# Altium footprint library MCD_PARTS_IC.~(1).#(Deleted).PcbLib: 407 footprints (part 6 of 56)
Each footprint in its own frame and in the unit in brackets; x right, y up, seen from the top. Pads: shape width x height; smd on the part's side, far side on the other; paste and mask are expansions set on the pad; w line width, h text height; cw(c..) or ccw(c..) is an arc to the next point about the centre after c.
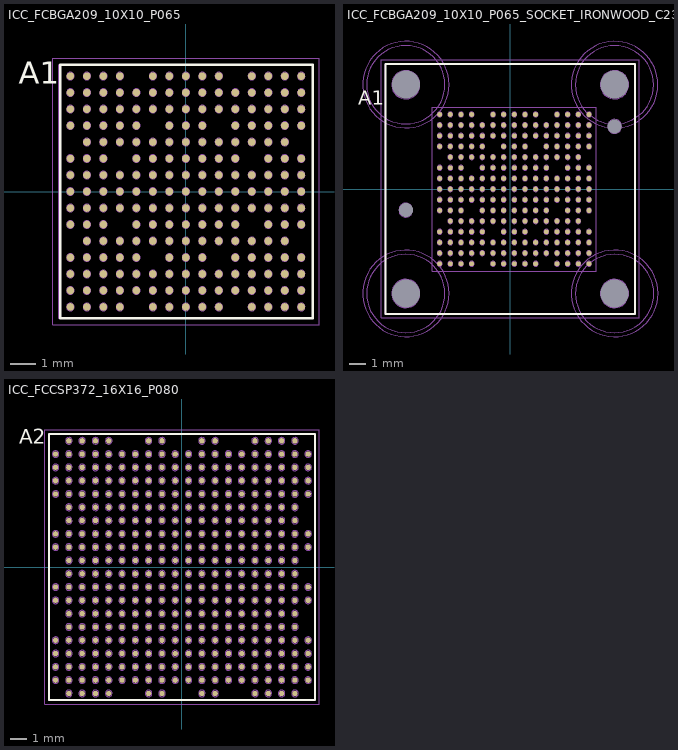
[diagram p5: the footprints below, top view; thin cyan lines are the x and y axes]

## ICC_FCBGA209_10X10_P065 [mm] "MCD-04280"
height 1.2
pads (209):
  round 0.3 smd mask+0.05: A1(-4.55,4.55) A2(-3.9,4.55) A3(-3.25,4.55) A4(-2.6,4.55) A6(-1.3,4.55) A7(-0.65,4.55) A8(0,4.55) A9(0.65,4.55) A10(1.3,4.55) A12(2.6,4.55) A13(3.25,4.55) A14(3.9,4.55) A15(4.55,4.55) B1(-4.55,3.9) B2(-3.9,3.9) B3(-3.25,3.9) B4(-2.6,3.9) B5(-1.95,3.9) B6(-1.3,3.9) B7(-0.65,3.9) B8(0,3.9) B9(0.65,3.9) B10(1.3,3.9) B11(1.95,3.9) B12(2.6,3.9) B13(3.25,3.9) B14(3.9,3.9) B15(4.55,3.9) C1(-4.55,3.25) C2(-3.9,3.25) C3(-3.25,3.25) C4(-2.6,3.25) C5(-1.95,3.25) C6(-1.3,3.25) C7(-0.65,3.25) C8(0,3.25) C9(0.65,3.25) C10(1.3,3.25) C11(1.95,3.25) C12(2.6,3.25) C13(3.25,3.25) C14(3.9,3.25) C15(4.55,3.25) D1(-4.55,2.6) D2(-3.9,2.6) D3(-3.25,2.6) D4(-2.6,2.6) D5(-1.95,2.6) D7(-0.65,2.6) D8(0,2.6) D9(0.65,2.6) D11(1.95,2.6) D12(2.6,2.6) D13(3.25,2.6) D14(3.9,2.6) D15(4.55,2.6) E2(-3.9,1.95) E3(-3.25,1.95) E4(-2.6,1.95) E5(-1.95,1.95) E6(-1.3,1.95) E7(-0.65,1.95) E8(0,1.95) E9(0.65,1.95) E10(1.3,1.95) E11(1.95,1.95) E12(2.6,1.95) E13(3.25,1.95) E14(3.9,1.95) F1(-4.55,1.3) F2(-3.9,1.3) F3(-3.25,1.3) F5(-1.95,1.3) F6(-1.3,1.3) F7(-0.65,1.3) F8(0,1.3) F9(0.65,1.3) F10(1.3,1.3) F11(1.95,1.3) F13(3.25,1.3) F14(3.9,1.3) F15(4.55,1.3) G1(-4.55,0.65) G2(-3.9,0.65) G3(-3.25,0.65) G4(-2.6,0.65) G5(-1.95,0.65) G6(-1.3,0.65) G7(-0.65,0.65) G8(0,0.65) G9(0.65,0.65) G10(1.3,0.65) G11(1.95,0.65) G12(2.6,0.65) G13(3.25,0.65) G14(3.9,0.65) G15(4.55,0.65) H1(-4.55,0) H2(-3.9,0) H3(-3.25,0) H4(-2.6,0) H5(-1.95,0) H6(-1.3,0) H7(-0.65,0) H8(0,0) H9(0.65,0) H10(1.3,0) H11(1.95,0) H12(2.6,0) H13(3.25,0) H14(3.9,0) H15(4.55,0) J1(-4.55,-0.65) J2(-3.9,-0.65) J3(-3.25,-0.65) J4(-2.6,-0.65) J5(-1.95,-0.65) J6(-1.3,-0.65) J7(-0.65,-0.65) J8(0,-0.65) J9(0.65,-0.65) J10(1.3,-0.65) J11(1.95,-0.65) J12(2.6,-0.65) J13(3.25,-0.65) J14(3.9,-0.65) J15(4.55,-0.65) K1(-4.55,-1.3) K2(-3.9,-1.3) K3(-3.25,-1.3) K5(-1.95,-1.3) K6(-1.3,-1.3) K7(-0.65,-1.3) K8(0,-1.3) K9(0.65,-1.3) K10(1.3,-1.3) K11(1.95,-1.3) K13(3.25,-1.3) K14(3.9,-1.3) K15(4.55,-1.3) L2(-3.9,-1.95) L3(-3.25,-1.95) L4(-2.6,-1.95) L5(-1.95,-1.95) L6(-1.3,-1.95) L7(-0.65,-1.95) L8(0,-1.95) L9(0.65,-1.95) L10(1.3,-1.95) L11(1.95,-1.95) L12(2.6,-1.95) L13(3.25,-1.95) L14(3.9,-1.95) M1(-4.55,-2.6) M2(-3.9,-2.6) M3(-3.25,-2.6) M4(-2.6,-2.6) M5(-1.95,-2.6) M7(-0.65,-2.6) M8(0,-2.6) M9(0.65,-2.6) M11(1.95,-2.6) M12(2.6,-2.6) M13(3.25,-2.6) M14(3.9,-2.6) M15(4.55,-2.6) N1(-4.55,-3.25) N2(-3.9,-3.25) N3(-3.25,-3.25) N4(-2.6,-3.25) N5(-1.95,-3.25) N6(-1.3,-3.25) N7(-0.65,-3.25) N8(0,-3.25) N9(0.65,-3.25) N10(1.3,-3.25) N11(1.95,-3.25) N12(2.6,-3.25) N13(3.25,-3.25) N14(3.9,-3.25) N15(4.55,-3.25) P1(-4.55,-3.9) P2(-3.9,-3.9) P3(-3.25,-3.9) P4(-2.6,-3.9) P5(-1.95,-3.9) P6(-1.3,-3.9) P7(-0.65,-3.9) P8(0,-3.9) P9(0.65,-3.9) P10(1.3,-3.9) P11(1.95,-3.9) P12(2.6,-3.9) P13(3.25,-3.9) P14(3.9,-3.9) P15(4.55,-3.9) R1(-4.55,-4.55) R2(-3.9,-4.55) R3(-3.25,-4.55) R4(-2.6,-4.55) R6(-1.3,-4.55) R7(-0.65,-4.55) R8(0,-4.55) R9(0.65,-4.55) R10(1.3,-4.55) R12(2.6,-4.55) R13(3.25,-4.55) R14(3.9,-4.55) R15(4.55,-4.55)
Top Overlay:
  lines w0.1: -4.95,-5 -4.95,5 5,5 5,-5 -4.95,-5
  text "A1" at -6.575,3.95 h1.5
M14-Top Assembly:
  drawing of 213 lines, arcs and shapes, not listed
  text "'.Designator'" at -2,-0.5 h0.75
  text "A1" at -4.95,4.325 h0.7
M16-Top Courtyard:
  lines w0.01: -5.25,-5.25 -5.25,5.25 5.25,5.25 5.25,-5.25 -5.25,-5.25
3D body: height 0.43, standoff 0, extent 1.085,-0.865 1.515,-0.435
3D body: height 0.43, standoff 0, extent 1.085,-1.515 1.515,-1.085
3D body: height 0.43, standoff 0, extent 0.435,-1.515 0.865,-1.085
3D body: height 0.43, standoff 0, extent -0.215,-1.515 0.215,-1.085
3D body: height 0.43, standoff 0, extent -0.865,-1.515 -0.435,-1.085
3D body: height 0.43, standoff 0, extent 1.085,-0.215 1.515,0.215
3D body: height 0.43, standoff 0, extent 0.435,-0.215 0.865,0.215
3D body: height 0.43, standoff 0, extent -0.215,-0.215 0.215,0.215
3D body: height 0.43, standoff 0, extent -0.865,-0.215 -0.435,0.215
3D body: height 0.43, standoff 0, extent -0.215,4.335 0.215,4.765
3D body: height 0.43, standoff 0, extent -0.865,4.335 -0.435,4.765
3D body: height 0.43, standoff 0, extent -1.515,4.335 -1.085,4.765
3D body: height 0.43, standoff 0, extent 1.085,0.435 1.515,0.865
3D body: height 0.43, standoff 0, extent 1.085,1.085 1.515,1.515
3D body: height 0.43, standoff 0, extent 1.085,1.735 1.515,2.165
3D body: height 0.43, standoff 0, extent 1.085,3.035 1.515,3.465
3D body: height 0.43, standoff 0, extent 1.085,3.685 1.515,4.115
3D body: height 0.43, standoff 0, extent 1.085,4.335 1.515,4.765
3D body: height 0.43, standoff 0, extent 0.435,0.435 0.865,0.865
3D body: height 0.43, standoff 0, extent 0.435,1.085 0.865,1.515
3D body: height 0.43, standoff 0, extent 0.435,1.735 0.865,2.165
3D body: height 0.43, standoff 0, extent 0.435,2.385 0.865,2.815
3D body: height 0.43, standoff 0, extent 0.435,3.035 0.865,3.465
3D body: height 0.43, standoff 0, extent 0.435,3.685 0.865,4.115
3D body: height 0.43, standoff 0, extent 0.435,4.335 0.865,4.765
3D body: height 0.43, standoff 0, extent 0.435,-0.865 0.865,-0.435
3D body: height 0.43, standoff 0, extent -0.215,-0.865 0.215,-0.435
3D body: height 0.43, standoff 0, extent -0.865,-0.865 -0.435,-0.435
3D body: height 0.43, standoff 0, extent 1.085,-4.765 1.515,-4.335
3D body: height 0.43, standoff 0, extent 1.085,-4.115 1.515,-3.685
3D body: height 0.43, standoff 0, extent 1.085,-3.465 1.515,-3.035
3D body: height 0.43, standoff 0, extent 1.085,-2.165 1.515,-1.735
3D body: height 0.43, standoff 0, extent 0.435,-4.765 0.865,-4.335
3D body: height 0.43, standoff 0, extent 0.435,-4.115 0.865,-3.685
3D body: height 0.43, standoff 0, extent 0.435,-3.465 0.865,-3.035
3D body: height 0.43, standoff 0, extent 0.435,-2.815 0.865,-2.385
3D body: height 0.43, standoff 0, extent 0.435,-2.165 0.865,-1.735
3D body: height 0.43, standoff 0, extent -0.215,-4.765 0.215,-4.335
3D body: height 0.43, standoff 0, extent -0.215,-4.115 0.215,-3.685
3D body: height 0.43, standoff 0, extent -0.215,-3.465 0.215,-3.035
3D body: height 0.43, standoff 0, extent -0.215,-2.815 0.215,-2.385
3D body: height 0.43, standoff 0, extent -0.215,-2.165 0.215,-1.735
3D body: height 0.43, standoff 0, extent -0.865,-4.765 -0.435,-4.335
3D body: height 0.43, standoff 0, extent -0.865,-4.115 -0.435,-3.685
3D body: height 0.43, standoff 0, extent -0.865,-3.465 -0.435,-3.035
3D body: height 0.43, standoff 0, extent -0.865,-2.815 -0.435,-2.385
3D body: height 0.43, standoff 0, extent -0.865,-2.165 -0.435,-1.735
3D body: height 0.43, standoff 0, extent -0.215,0.435 0.215,0.865
3D body: height 0.43, standoff 0, extent -0.215,1.085 0.215,1.515
3D body: height 0.43, standoff 0, extent -0.215,1.735 0.215,2.165
3D body: height 0.43, standoff 0, extent -0.215,2.385 0.215,2.815
3D body: height 0.43, standoff 0, extent -0.215,3.035 0.215,3.465
3D body: height 0.43, standoff 0, extent -0.215,3.685 0.215,4.115
3D body: height 0.43, standoff 0, extent -0.865,0.435 -0.435,0.865
3D body: height 0.43, standoff 0, extent -0.865,1.085 -0.435,1.515
3D body: height 0.43, standoff 0, extent -0.865,1.735 -0.435,2.165
3D body: height 0.43, standoff 0, extent -0.865,2.385 -0.435,2.815
3D body: height 0.43, standoff 0, extent -0.865,3.035 -0.435,3.465
3D body: height 0.43, standoff 0, extent -0.865,3.685 -0.435,4.115
3D body: height 0.43, standoff 0, extent -1.515,-4.765 -1.085,-4.335
3D body: height 0.43, standoff 0, extent -1.515,-4.115 -1.085,-3.685
3D body: height 0.43, standoff 0, extent -1.515,-3.465 -1.085,-3.035
3D body: height 0.43, standoff 0, extent -1.515,-2.165 -1.085,-1.735
3D body: height 0.43, standoff 0, extent -1.515,-1.515 -1.085,-1.085
3D body: height 0.43, standoff 0, extent -1.515,-0.865 -1.085,-0.435
3D body: height 0.43, standoff 0, extent -1.515,-0.215 -1.085,0.215
3D body: height 0.43, standoff 0, extent -1.515,0.435 -1.085,0.865
3D body: height 0.43, standoff 0, extent -1.515,1.085 -1.085,1.515
3D body: height 0.43, standoff 0, extent -1.515,1.735 -1.085,2.165
3D body: height 0.43, standoff 0, extent -1.515,3.035 -1.085,3.465
3D body: height 0.43, standoff 0, extent -1.515,3.685 -1.085,4.115
3D body: height 0.43, standoff 0, extent -2.165,-4.115 -1.735,-3.685
3D body: height 0.43, standoff 0, extent -2.165,-3.465 -1.735,-3.035
3D body: height 0.43, standoff 0, extent -2.165,-2.815 -1.735,-2.385
3D body: height 0.43, standoff 0, extent -2.165,-2.165 -1.735,-1.735
3D body: height 0.43, standoff 0, extent -2.165,-1.515 -1.735,-1.085
3D body: height 0.43, standoff 0, extent -2.165,-0.865 -1.735,-0.435
3D body: height 0.43, standoff 0, extent -2.165,-0.215 -1.735,0.215
3D body: height 0.43, standoff 0, extent -2.165,0.435 -1.735,0.865
3D body: height 0.43, standoff 0, extent -2.165,1.085 -1.735,1.515
3D body: height 0.43, standoff 0, extent -2.165,1.735 -1.735,2.165
3D body: height 0.43, standoff 0, extent -2.165,2.385 -1.735,2.815
3D body: height 0.43, standoff 0, extent -2.165,3.035 -1.735,3.465
3D body: height 0.43, standoff 0, extent -2.165,3.685 -1.735,4.115
3D body: height 0.43, standoff 0, extent -2.815,-4.765 -2.385,-4.335
3D body: height 0.43, standoff 0, extent -2.815,-4.115 -2.385,-3.685
3D body: height 0.43, standoff 0, extent -2.815,-3.465 -2.385,-3.035
3D body: height 0.43, standoff 0, extent -2.815,-2.815 -2.385,-2.385
3D body: height 0.43, standoff 0, extent -2.815,-2.165 -2.385,-1.735
3D body: height 0.43, standoff 0, extent -2.815,-0.865 -2.385,-0.435
3D body: height 0.43, standoff 0, extent -2.815,-0.215 -2.385,0.215
3D body: height 0.43, standoff 0, extent -2.815,0.435 -2.385,0.865
3D body: height 0.43, standoff 0, extent -2.815,1.735 -2.385,2.165
3D body: height 0.43, standoff 0, extent -2.815,2.385 -2.385,2.815
3D body: height 0.43, standoff 0, extent -2.815,3.035 -2.385,3.465
3D body: height 0.43, standoff 0, extent -2.815,3.685 -2.385,4.115
3D body: height 0.43, standoff 0, extent -2.815,4.335 -2.385,4.765
3D body: height 0.43, standoff 0, extent -3.465,-4.765 -3.035,-4.335
3D body: height 0.43, standoff 0, extent -3.465,-4.115 -3.035,-3.685
3D body: height 0.43, standoff 0, extent -3.465,-3.465 -3.035,-3.035
3D body: height 0.43, standoff 0, extent -3.465,-2.815 -3.035,-2.385
3D body: height 0.43, standoff 0, extent -3.465,-2.165 -3.035,-1.735
3D body: height 0.43, standoff 0, extent -3.465,-1.515 -3.035,-1.085
3D body: height 0.43, standoff 0, extent -3.465,-0.865 -3.035,-0.435
3D body: height 0.43, standoff 0, extent -3.465,-0.215 -3.035,0.215
3D body: height 0.43, standoff 0, extent -3.465,0.435 -3.035,0.865
3D body: height 0.43, standoff 0, extent -3.465,1.085 -3.035,1.515
3D body: height 0.43, standoff 0, extent -3.465,1.735 -3.035,2.165
3D body: height 0.43, standoff 0, extent -3.465,2.385 -3.035,2.815
3D body: height 0.43, standoff 0, extent -3.465,3.035 -3.035,3.465
3D body: height 0.43, standoff 0, extent -3.465,3.685 -3.035,4.115
3D body: height 0.43, standoff 0, extent -3.465,4.335 -3.035,4.765
3D body: height 0.43, standoff 0, extent -4.115,-4.765 -3.685,-4.335
3D body: height 0.43, standoff 0, extent -4.115,-4.115 -3.685,-3.685
3D body: height 0.43, standoff 0, extent -4.115,-3.465 -3.685,-3.035
3D body: height 0.43, standoff 0, extent -4.115,-2.815 -3.685,-2.385
3D body: height 0.43, standoff 0, extent -4.115,-2.165 -3.685,-1.735
3D body: height 0.43, standoff 0, extent -4.115,-1.515 -3.685,-1.085
3D body: height 0.43, standoff 0, extent -4.115,-0.865 -3.685,-0.435
3D body: height 0.43, standoff 0, extent -4.115,-0.215 -3.685,0.215
3D body: height 0.43, standoff 0, extent -4.115,0.435 -3.685,0.865
3D body: height 0.43, standoff 0, extent -4.115,1.085 -3.685,1.515
3D body: height 0.43, standoff 0, extent -4.115,1.735 -3.685,2.165
3D body: height 0.43, standoff 0, extent -4.115,2.385 -3.685,2.815
3D body: height 0.43, standoff 0, extent -4.115,3.035 -3.685,3.465
3D body: height 0.43, standoff 0, extent -4.115,3.685 -3.685,4.115
3D body: height 0.43, standoff 0, extent -4.115,4.335 -3.685,4.765
3D body: height 0.43, standoff 0, extent -4.765,-4.765 -4.335,-4.335
3D body: height 0.43, standoff 0, extent -4.765,-4.115 -4.335,-3.685
3D body: height 0.43, standoff 0, extent -4.765,-3.465 -4.335,-3.035
3D body: height 0.43, standoff 0, extent -4.765,-2.815 -4.335,-2.385
3D body: height 0.43, standoff 0, extent -4.765,-1.515 -4.335,-1.085
3D body: height 0.43, standoff 0, extent -4.765,-0.865 -4.335,-0.435
3D body: height 0.43, standoff 0, extent -4.765,-0.215 -4.335,0.215
3D body: height 0.43, standoff 0, extent -4.765,0.435 -4.335,0.865
3D body: height 0.43, standoff 0, extent -4.765,1.085 -4.335,1.515
3D body: height 0.43, standoff 0, extent -4.765,2.385 -4.335,2.815
3D body: height 0.43, standoff 0, extent -4.765,3.035 -4.335,3.465
3D body: height 0.43, standoff 0, extent -4.765,3.685 -4.335,4.115
3D body: height 0.43, standoff 0, extent -4.765,4.335 -4.335,4.765
3D body: height 1.2, standoff 0.24, extent -5,-5 5,5
3D body: height 1.21, standoff 1.2, extent -4.617,3.683 -3.683,4.617
3D body: height 0.43, standoff 0, extent 4.335,-0.865 4.765,-0.435
3D body: height 0.43, standoff 0, extent 4.335,-1.515 4.765,-1.085
3D body: height 0.43, standoff 0, extent 3.685,-1.515 4.115,-1.085
3D body: height 0.43, standoff 0, extent 3.035,-1.515 3.465,-1.085
3D body: height 0.43, standoff 0, extent 4.335,-0.215 4.765,0.215
3D body: height 0.43, standoff 0, extent 3.685,-0.215 4.115,0.215
3D body: height 0.43, standoff 0, extent 3.035,-0.215 3.465,0.215
3D body: height 0.43, standoff 0, extent 2.385,-0.215 2.815,0.215
3D body: height 0.43, standoff 0, extent 3.035,4.335 3.465,4.765
3D body: height 0.43, standoff 0, extent 2.385,4.335 2.815,4.765
3D body: height 0.43, standoff 0, extent 4.335,0.435 4.765,0.865
3D body: height 0.43, standoff 0, extent 4.335,1.085 4.765,1.515
3D body: height 0.43, standoff 0, extent 4.335,2.385 4.765,2.815
3D body: height 0.43, standoff 0, extent 4.335,3.035 4.765,3.465
3D body: height 0.43, standoff 0, extent 4.335,3.685 4.765,4.115
3D body: height 0.43, standoff 0, extent 4.335,4.335 4.765,4.765
3D body: height 0.43, standoff 0, extent 3.685,0.435 4.115,0.865
3D body: height 0.43, standoff 0, extent 3.685,1.085 4.115,1.515
3D body: height 0.43, standoff 0, extent 3.685,1.735 4.115,2.165
3D body: height 0.43, standoff 0, extent 3.685,2.385 4.115,2.815
3D body: height 0.43, standoff 0, extent 3.685,3.035 4.115,3.465
3D body: height 0.43, standoff 0, extent 3.685,3.685 4.115,4.115
3D body: height 0.43, standoff 0, extent 3.685,4.335 4.115,4.765
3D body: height 0.43, standoff 0, extent 3.685,-0.865 4.115,-0.435
3D body: height 0.43, standoff 0, extent 3.035,-0.865 3.465,-0.435
3D body: height 0.43, standoff 0, extent 2.385,-0.865 2.815,-0.435
3D body: height 0.43, standoff 0, extent 4.335,-4.765 4.765,-4.335
3D body: height 0.43, standoff 0, extent 4.335,-4.115 4.765,-3.685
3D body: height 0.43, standoff 0, extent 4.335,-3.465 4.765,-3.035
3D body: height 0.43, standoff 0, extent 4.335,-2.815 4.765,-2.385
3D body: height 0.43, standoff 0, extent 3.685,-4.765 4.115,-4.335
3D body: height 0.43, standoff 0, extent 3.685,-4.115 4.115,-3.685
3D body: height 0.43, standoff 0, extent 3.685,-3.465 4.115,-3.035
3D body: height 0.43, standoff 0, extent 3.685,-2.815 4.115,-2.385
3D body: height 0.43, standoff 0, extent 3.685,-2.165 4.115,-1.735
3D body: height 0.43, standoff 0, extent 3.035,-4.765 3.465,-4.335
3D body: height 0.43, standoff 0, extent 3.035,-4.115 3.465,-3.685
3D body: height 0.43, standoff 0, extent 3.035,-3.465 3.465,-3.035
3D body: height 0.43, standoff 0, extent 3.035,-2.815 3.465,-2.385
3D body: height 0.43, standoff 0, extent 3.035,-2.165 3.465,-1.735
3D body: height 0.43, standoff 0, extent 2.385,-4.765 2.815,-4.335
3D body: height 0.43, standoff 0, extent 2.385,-4.115 2.815,-3.685
3D body: height 0.43, standoff 0, extent 2.385,-3.465 2.815,-3.035
3D body: height 0.43, standoff 0, extent 2.385,-2.815 2.815,-2.385
3D body: height 0.43, standoff 0, extent 2.385,-2.165 2.815,-1.735
3D body: height 0.43, standoff 0, extent 3.035,0.435 3.465,0.865
3D body: height 0.43, standoff 0, extent 3.035,1.085 3.465,1.515
3D body: height 0.43, standoff 0, extent 3.035,1.735 3.465,2.165
3D body: height 0.43, standoff 0, extent 3.035,2.385 3.465,2.815
3D body: height 0.43, standoff 0, extent 3.035,3.035 3.465,3.465
3D body: height 0.43, standoff 0, extent 3.035,3.685 3.465,4.115
3D body: height 0.43, standoff 0, extent 2.385,0.435 2.815,0.865
3D body: height 0.43, standoff 0, extent 2.385,1.735 2.815,2.165
3D body: height 0.43, standoff 0, extent 2.385,2.385 2.815,2.815
3D body: height 0.43, standoff 0, extent 2.385,3.035 2.815,3.465
3D body: height 0.43, standoff 0, extent 2.385,3.685 2.815,4.115
3D body: height 0.43, standoff 0, extent 1.735,-4.115 2.165,-3.685
3D body: height 0.43, standoff 0, extent 1.735,-3.465 2.165,-3.035
3D body: height 0.43, standoff 0, extent 1.735,-2.815 2.165,-2.385
3D body: height 0.43, standoff 0, extent 1.735,-2.165 2.165,-1.735
3D body: height 0.43, standoff 0, extent 1.735,-1.515 2.165,-1.085
3D body: height 0.43, standoff 0, extent 1.735,-0.865 2.165,-0.435
3D body: height 0.43, standoff 0, extent 1.735,-0.215 2.165,0.215
3D body: height 0.43, standoff 0, extent 1.735,0.435 2.165,0.865
3D body: height 0.43, standoff 0, extent 1.735,1.085 2.165,1.515
3D body: height 0.43, standoff 0, extent 1.735,1.735 2.165,2.165
3D body: height 0.43, standoff 0, extent 1.735,2.385 2.165,2.815
3D body: height 0.43, standoff 0, extent 1.735,3.035 2.165,3.465
3D body: height 0.43, standoff 0, extent 1.735,3.685 2.165,4.115

## ICC_FCBGA209_10X10_P065_SOCKET_IRONWOOD_C23913 [mm] "MCD-04280"
height 9.88
pads (215):
  round 0.3 smd mask+0.05: A1(-4.3,4.55) A2(-3.65,4.55) A3(-3,4.55) A4(-2.35,4.55) A6(-1.05,4.55) A7(-0.4,4.55) A8(0.25,4.55) A9(0.9,4.55) A10(1.55,4.55) A12(2.85,4.55) A13(3.5,4.55) A14(4.15,4.55) A15(4.8,4.55) B1(-4.3,3.9) B2(-3.65,3.9) B3(-3,3.9) B4(-2.35,3.9) B5(-1.7,3.9) B6(-1.05,3.9) B7(-0.4,3.9) B8(0.25,3.9) B9(0.9,3.9) B10(1.55,3.9) B11(2.2,3.9) B12(2.85,3.9) B13(3.5,3.9) B14(4.15,3.9) B15(4.8,3.9) C1(-4.3,3.25) C2(-3.65,3.25) C3(-3,3.25) C4(-2.35,3.25) C5(-1.7,3.25) C6(-1.05,3.25) C7(-0.4,3.25) C8(0.25,3.25) C9(0.9,3.25) C10(1.55,3.25) C11(2.2,3.25) C12(2.85,3.25) C13(3.5,3.25) C14(4.15,3.25) C15(4.8,3.25) D1(-4.3,2.6) D2(-3.65,2.6) D3(-3,2.6) D4(-2.35,2.6) D5(-1.7,2.6) D7(-0.4,2.6) D8(0.25,2.6) D9(0.9,2.6) D11(2.2,2.6) D12(2.85,2.6) D13(3.5,2.6) D14(4.15,2.6) D15(4.8,2.6) E2(-3.65,1.95) E3(-3,1.95) E4(-2.35,1.95) E5(-1.7,1.95) E6(-1.05,1.95) E7(-0.4,1.95) E8(0.25,1.95) E9(0.9,1.95) E10(1.55,1.95) E11(2.2,1.95) E12(2.85,1.95) E13(3.5,1.95) E14(4.15,1.95) F1(-4.3,1.3) F2(-3.65,1.3) F3(-3,1.3) F5(-1.7,1.3) F6(-1.05,1.3) F7(-0.4,1.3) F8(0.25,1.3) F9(0.9,1.3) F10(1.55,1.3) F11(2.2,1.3) F13(3.5,1.3) F14(4.15,1.3) F15(4.8,1.3) G1(-4.3,0.65) G2(-3.65,0.65) G3(-3,0.65) G4(-2.35,0.65) G5(-1.7,0.65) G6(-1.05,0.65) G7(-0.4,0.65) G8(0.25,0.65) G9(0.9,0.65) G10(1.55,0.65) G11(2.2,0.65) G12(2.85,0.65) G13(3.5,0.65) G14(4.15,0.65) G15(4.8,0.65) H1(-4.3,0) H2(-3.65,0) H3(-3,0) H4(-2.35,0) H5(-1.7,0) H6(-1.05,0) H7(-0.4,0) H8(0.25,0) H9(0.9,0) H10(1.55,0) H11(2.2,0) H12(2.85,0) H13(3.5,0) H14(4.15,0) H15(4.8,0) J1(-4.3,-0.65) J2(-3.65,-0.65) J3(-3,-0.65) J4(-2.35,-0.65) J5(-1.7,-0.65) J6(-1.05,-0.65) J7(-0.4,-0.65) J8(0.25,-0.65) J9(0.9,-0.65) J10(1.55,-0.65) J11(2.2,-0.65) J12(2.85,-0.65) J13(3.5,-0.65) J14(4.15,-0.65) J15(4.8,-0.65) K1(-4.3,-1.3) K2(-3.65,-1.3) K3(-3,-1.3) K5(-1.7,-1.3) K6(-1.05,-1.3) K7(-0.4,-1.3) K8(0.25,-1.3) K9(0.9,-1.3) K10(1.55,-1.3) K11(2.2,-1.3) K13(3.5,-1.3) K14(4.15,-1.3) K15(4.8,-1.3) L2(-3.65,-1.95) L3(-3,-1.95) L4(-2.35,-1.95) L5(-1.7,-1.95) L6(-1.05,-1.95) L7(-0.4,-1.95) L8(0.25,-1.95) L9(0.9,-1.95) L10(1.55,-1.95) L11(2.2,-1.95) L12(2.85,-1.95) L13(3.5,-1.95) L14(4.15,-1.95) M1(-4.3,-2.6) M2(-3.65,-2.6) M3(-3,-2.6) M4(-2.35,-2.6) M5(-1.7,-2.6) M7(-0.4,-2.6) M8(0.25,-2.6) M9(0.9,-2.6) M11(2.2,-2.6) M12(2.85,-2.6) M13(3.5,-2.6) M14(4.15,-2.6) M15(4.8,-2.6) N1(-4.3,-3.25) N2(-3.65,-3.25) N3(-3,-3.25) N4(-2.35,-3.25) N5(-1.7,-3.25) N6(-1.05,-3.25) N7(-0.4,-3.25) N8(0.25,-3.25) N9(0.9,-3.25) N10(1.55,-3.25) N11(2.2,-3.25) N12(2.85,-3.25) N13(3.5,-3.25) N14(4.15,-3.25) N15(4.8,-3.25) P1(-4.3,-3.9) P2(-3.65,-3.9) P3(-3,-3.9) P4(-2.35,-3.9) P5(-1.7,-3.9) P6(-1.05,-3.9) P7(-0.4,-3.9) P8(0.25,-3.9) P9(0.9,-3.9) P10(1.55,-3.9) P11(2.2,-3.9) P12(2.85,-3.9) P13(3.5,-3.9) P14(4.15,-3.9) P15(4.8,-3.9) R1(-4.3,-4.55) R2(-3.65,-4.55) R3(-3,-4.55) R4(-2.35,-4.55) R6(-1.05,-4.55) R7(-0.4,-4.55) R8(0.25,-4.55) R9(0.9,-4.55) R10(1.55,-4.55) R12(2.85,-4.55) R13(3.5,-4.55) R14(4.15,-4.55) R15(4.8,-4.55)
  round 0 hole 0.85 unplated mask+0.05: NPTH1(6.363,3.823) NPTH2(-6.362,-1.282)
  round 0 hole 1.71 unplated mask+0.05: PTH1(-6.362,-6.362) PTH1(-6.362,6.363) PTH1(6.363,-6.362) PTH1(6.363,6.363)
Top Overlay:
  lines w0.12: -7.612,-7.612 -7.612,7.613 7.613,7.613 7.613,-7.612 -7.612,-7.612
  text "A1" at -9.275,4.825 h1.5
Bottom Overlay:
  circle w0.12: c-6.355,6.369 r2.513
  circle w0.12: c-6.363,-6.363 r2.513
  circle w0.12: c6.369,-6.356 r2.513
  lines w0.12: 5.692,3.941 cw(c6.363,6.363) 7.069,3.951
M14-Top Assembly:
  drawing of 227 lines, arcs and shapes, not listed
  text "'.Designator'" at -1.75,-0.5 h0.75
  text "A1" at -4.7,4.325 h0.7
M15-Bottom Assembly:
  circle w0.01: c-6.362,6.363 r2.388
  circle w0.01: c-6.363,-6.363 r2.388
  circle w0.01: c6.362,-6.363 r2.388
  circle w0.01: c6.355,6.356 r2.388
M16-Top Courtyard:
  lines w0.01: -7.85,-7.85 -7.85,7.875 7.875,7.875 7.875,-7.85 -7.85,-7.85
M17-Bottom Courtyard:
  circle w0.01: c-6.355,6.369 r2.638
  circle w0.01: c-6.356,-6.356 r2.638
  circle w0.01: c6.369,-6.356 r2.638
  circle w0.01: c6.363,6.363 r2.638
3D body: height 9.88, standoff 0, extent -7.623,-7.612 7.613,7.613
3D body: height 4.13, standoff 0, extent 3.968,3.968 8.743,8.743
3D body: height 4.13, standoff 0, extent -8.75,3.975 -3.975,8.75
3D body: height 4.13, standoff 0, extent -8.75,-8.75 -3.975,-3.975
3D body: height 4.13, standoff 0, extent 3.975,-8.75 8.75,-3.975

## ICC_FCCSP372_16X16_P080 [mm] "MCD-04310"
height 1.2
pads (372):
  round 0.32 smd mask+0.05: A2(-6.8,7.6) A3(-6,7.6) A4(-5.2,7.6) A5(-4.4,7.6) A8(-2,7.6) A9(-1.2,7.6) A12(1.2,7.6) A13(2,7.6) A16(4.4,7.6) A17(5.2,7.6) A18(6,7.6) A19(6.8,7.6) B1(-7.6,6.8) B2(-6.8,6.8) B3(-6,6.8) B4(-5.2,6.8) B5(-4.4,6.8) B6(-3.6,6.8) B7(-2.8,6.8) B8(-2,6.8) B9(-1.2,6.8) B10(-0.4,6.8) B11(0.4,6.8) B12(1.2,6.8) B13(2,6.8) B14(2.8,6.8) B15(3.6,6.8) B16(4.4,6.8) B17(5.2,6.8) B18(6,6.8) B19(6.8,6.8) B20(7.6,6.8) C1(-7.6,6) C2(-6.8,6) C3(-6,6) C4(-5.2,6) C5(-4.4,6) C6(-3.6,6) C7(-2.8,6) C8(-2,6) C9(-1.2,6) C10(-0.4,6) C11(0.4,6) C12(1.2,6) C13(2,6) C14(2.8,6) C15(3.6,6) C16(4.4,6) C17(5.2,6) C18(6,6) C19(6.8,6) C20(7.6,6) D1(-7.6,5.2) D2(-6.8,5.2) D3(-6,5.2) D4(-5.2,5.2) D5(-4.4,5.2) D6(-3.6,5.2) D7(-2.8,5.2) D8(-2,5.2) D9(-1.2,5.2) D10(-0.4,5.2) D11(0.4,5.2) D12(1.2,5.2) D13(2,5.2) D14(2.8,5.2) D15(3.6,5.2) D16(4.4,5.2) D17(5.2,5.2) D18(6,5.2) D19(6.8,5.2) D20(7.6,5.2) E1(-7.6,4.4) E2(-6.8,4.4) E3(-6,4.4) E4(-5.2,4.4) E5(-4.4,4.4) E6(-3.6,4.4) E7(-2.8,4.4) E8(-2,4.4) E9(-1.2,4.4) E10(-0.4,4.4) E11(0.4,4.4) E12(1.2,4.4) E13(2,4.4) E14(2.8,4.4) E15(3.6,4.4) E16(4.4,4.4) E17(5.2,4.4) E18(6,4.4) E19(6.8,4.4) E20(7.6,4.4) F2(-6.8,3.6) F3(-6,3.6) F4(-5.2,3.6) F5(-4.4,3.6) F6(-3.6,3.6) F7(-2.8,3.6) F8(-2,3.6) F9(-1.2,3.6) F10(-0.4,3.6) F11(0.4,3.6) F12(1.2,3.6) F13(2,3.6) F14(2.8,3.6) F15(3.6,3.6) F16(4.4,3.6) F17(5.2,3.6) F18(6,3.6) F19(6.8,3.6) G2(-6.8,2.8) G3(-6,2.8) G4(-5.2,2.8) G5(-4.4,2.8) G6(-3.6,2.8) G7(-2.8,2.8) G8(-2,2.8) G9(-1.2,2.8) G10(-0.4,2.8) G11(0.4,2.8) G12(1.2,2.8) G13(2,2.8) G14(2.8,2.8) G15(3.6,2.8) G16(4.4,2.8) G17(5.2,2.8) G18(6,2.8) G19(6.8,2.8) H1(-7.6,2) H2(-6.8,2) H3(-6,2) H4(-5.2,2) H5(-4.4,2) H6(-3.6,2) H7(-2.8,2) H8(-2,2) H9(-1.2,2) H10(-0.4,2) H11(0.4,2) H12(1.2,2) H13(2,2) H14(2.8,2) H15(3.6,2) H16(4.4,2) H17(5.2,2) H18(6,2) H19(6.8,2) H20(7.6,2) J1(-7.6,1.2) J2(-6.8,1.2) J3(-6,1.2) J4(-5.2,1.2) J5(-4.4,1.2) J6(-3.6,1.2) J7(-2.8,1.2) J8(-2,1.2) J9(-1.2,1.2) J10(-0.4,1.2) J11(0.4,1.2) J12(1.2,1.2) J13(2,1.2) J14(2.8,1.2) J15(3.6,1.2) J16(4.4,1.2) J17(5.2,1.2) J18(6,1.2) J19(6.8,1.2) J20(7.6,1.2) K2(-6.8,0.4) K3(-6,0.4) K4(-5.2,0.4) K5(-4.4,0.4) K6(-3.6,0.4) K7(-2.8,0.4) K8(-2,0.4) K9(-1.2,0.4) K10(-0.4,0.4) K11(0.4,0.4) K12(1.2,0.4) K13(2,0.4) K14(2.8,0.4) K15(3.6,0.4) K16(4.4,0.4) K17(5.2,0.4) K18(6,0.4) K19(6.8,0.4) L2(-6.8,-0.4) L3(-6,-0.4) L4(-5.2,-0.4) L5(-4.4,-0.4) L6(-3.6,-0.4) L7(-2.8,-0.4) L8(-2,-0.4) L9(-1.2,-0.4) L10(-0.4,-0.4) L11(0.4,-0.4) L12(1.2,-0.4) L13(2,-0.4) L14(2.8,-0.4) L15(3.6,-0.4) L16(4.4,-0.4) L17(5.2,-0.4) L18(6,-0.4) L19(6.8,-0.4) M1(-7.6,-1.2) M2(-6.8,-1.2) M3(-6,-1.2) M4(-5.2,-1.2) M5(-4.4,-1.2) M6(-3.6,-1.2) M7(-2.8,-1.2) M8(-2,-1.2) M9(-1.2,-1.2) M10(-0.4,-1.2) M11(0.4,-1.2) M12(1.2,-1.2) M13(2,-1.2) M14(2.8,-1.2) M15(3.6,-1.2) M16(4.4,-1.2) M17(5.2,-1.2) M18(6,-1.2) M19(6.8,-1.2) M20(7.6,-1.2) N1(-7.6,-2) N2(-6.8,-2) N3(-6,-2) N4(-5.2,-2) N5(-4.4,-2) N6(-3.6,-2) N7(-2.8,-2) N8(-2,-2) N9(-1.2,-2) N10(-0.4,-2) N11(0.4,-2) N12(1.2,-2) N13(2,-2) N14(2.8,-2) N15(3.6,-2) N16(4.4,-2) N17(5.2,-2) N18(6,-2) N19(6.8,-2) N20(7.6,-2) P2(-6.8,-2.8) P3(-6,-2.8) P4(-5.2,-2.8) P5(-4.4,-2.8) P6(-3.6,-2.8) P7(-2.8,-2.8) P8(-2,-2.8) P9(-1.2,-2.8) P10(-0.4,-2.8) P11(0.4,-2.8) P12(1.2,-2.8) P13(2,-2.8) P14(2.8,-2.8) P15(3.6,-2.8) P16(4.4,-2.8) P17(5.2,-2.8) P18(6,-2.8) P19(6.8,-2.8) R2(-6.8,-3.6) R3(-6,-3.6) R4(-5.2,-3.6) R5(-4.4,-3.6) R6(-3.6,-3.6) R7(-2.8,-3.6) R8(-2,-3.6) R9(-1.2,-3.6) R10(-0.4,-3.6) R11(0.4,-3.6) R12(1.2,-3.6) R13(2,-3.6) R14(2.8,-3.6) R15(3.6,-3.6) R16(4.4,-3.6) R17(5.2,-3.6) R18(6,-3.6) R19(6.8,-3.6) T1(-7.6,-4.4) T2(-6.8,-4.4) T3(-6,-4.4) T4(-5.2,-4.4) T5(-4.4,-4.4) T6(-3.6,-4.4) T7(-2.8,-4.4) T8(-2,-4.4) T9(-1.2,-4.4) T10(-0.4,-4.4) T11(0.4,-4.4) T12(1.2,-4.4) T13(2,-4.4) T14(2.8,-4.4) T15(3.6,-4.4) T16(4.4,-4.4) T17(5.2,-4.4) T18(6,-4.4) T19(6.8,-4.4) T20(7.6,-4.4) U1(-7.6,-5.2) U2(-6.8,-5.2) U3(-6,-5.2) U4(-5.2,-5.2) U5(-4.4,-5.2) U6(-3.6,-5.2) U7(-2.8,-5.2) U8(-2,-5.2) U9(-1.2,-5.2) U10(-0.4,-5.2) U11(0.4,-5.2) U12(1.2,-5.2) U13(2,-5.2) U14(2.8,-5.2) U15(3.6,-5.2) U16(4.4,-5.2) U17(5.2,-5.2) U18(6,-5.2) U19(6.8,-5.2) U20(7.6,-5.2) V1(-7.6,-6) V2(-6.8,-6) V3(-6,-6) V4(-5.2,-6) V5(-4.4,-6) V6(-3.6,-6) V7(-2.8,-6) V8(-2,-6) V9(-1.2,-6) V10(-0.4,-6) V11(0.4,-6) V12(1.2,-6) V13(2,-6) V14(2.8,-6) V15(3.6,-6) V16(4.4,-6) V17(5.2,-6) V18(6,-6) V19(6.8,-6) V20(7.6,-6) W1(-7.6,-6.8) W2(-6.8,-6.8) W3(-6,-6.8) W4(-5.2,-6.8) W5(-4.4,-6.8) W6(-3.6,-6.8) W7(-2.8,-6.8) W8(-2,-6.8) W9(-1.2,-6.8) W10(-0.4,-6.8) W11(0.4,-6.8) W12(1.2,-6.8) W13(2,-6.8) W14(2.8,-6.8) W15(3.6,-6.8) W16(4.4,-6.8) W17(5.2,-6.8) W18(6,-6.8) W19(6.8,-6.8) W20(7.6,-6.8) Y2(-6.8,-7.6) Y3(-6,-7.6) Y4(-5.2,-7.6) Y5(-4.4,-7.6) Y8(-2,-7.6) Y9(-1.2,-7.6) Y12(1.2,-7.6) Y13(2,-7.6) Y16(4.4,-7.6) Y17(5.2,-7.6) Y18(6,-7.6) Y19(6.8,-7.6)
Top Overlay:
  lines w0.12: -8,-8 8,-8 8,8 -8,8 -8,-8
  text "A2" at -9.8,7.125 h1.5
M14-Top Assembly:
  drawing of 376 lines, arcs and shapes, not listed
  text "A2" at -7.25,7.375 h0.75
  text "'.Designator'" at -2,-0.5 h0.75
M16-Top Courtyard:
  lines w0.01: -8.25,-8.25 8.25,-8.25 8.25,8.25 -8.25,8.25 -8.25,-8.25
3D body: height 1.2, standoff 0.24, extent -8,-8 8,8
3D body: height 0.4, standoff 0, extent -7,7.4 -6.6,7.8
3D body: height 0.4, standoff 0, extent -6.2,7.4 -5.8,7.8
3D body: height 0.4, standoff 0, extent -5.4,7.4 -5,7.8
3D body: height 0.4, standoff 0, extent -4.6,7.4 -4.2,7.8
3D body: height 0.4, standoff 0, extent -2.2,7.4 -1.8,7.8
3D body: height 0.4, standoff 0, extent -1.4,7.4 -1,7.8
3D body: height 0.4, standoff 0, extent 1,7.4 1.4,7.8
3D body: height 0.4, standoff 0, extent 1.8,7.4 2.2,7.8
3D body: height 0.4, standoff 0, extent 4.2,7.4 4.6,7.8
3D body: height 0.4, standoff 0, extent 5,7.4 5.4,7.8
3D body: height 0.4, standoff 0, extent 5.8,7.4 6.2,7.8
3D body: height 0.4, standoff 0, extent 6.6,7.4 7,7.8
3D body: height 0.4, standoff 0, extent -7.8,6.6 -7.4,7
3D body: height 0.4, standoff 0, extent -7,6.6 -6.6,7
3D body: height 0.4, standoff 0, extent -6.2,6.6 -5.8,7
3D body: height 0.4, standoff 0, extent -5.4,6.6 -5,7
3D body: height 0.4, standoff 0, extent -4.6,6.6 -4.2,7
3D body: height 0.4, standoff 0, extent -3.8,6.6 -3.4,7
3D body: height 0.4, standoff 0, extent -3,6.6 -2.6,7
3D body: height 0.4, standoff 0, extent -2.2,6.6 -1.8,7
3D body: height 0.4, standoff 0, extent -1.4,6.6 -1,7
3D body: height 0.4, standoff 0, extent -0.6,6.6 -0.2,7
3D body: height 0.4, standoff 0, extent 0.2,6.6 0.6,7
3D body: height 0.4, standoff 0, extent 1,6.6 1.4,7
3D body: height 0.4, standoff 0, extent 1.8,6.6 2.2,7
3D body: height 0.4, standoff 0, extent 2.6,6.6 3,7
3D body: height 0.4, standoff 0, extent 3.4,6.6 3.8,7
3D body: height 0.4, standoff 0, extent 4.2,6.6 4.6,7
3D body: height 0.4, standoff 0, extent 5,6.6 5.4,7
3D body: height 0.4, standoff 0, extent 5.8,6.6 6.2,7
3D body: height 0.4, standoff 0, extent 6.6,6.6 7,7
3D body: height 0.4, standoff 0, extent 7.4,6.6 7.8,7
3D body: height 0.4, standoff 0, extent -7.8,5.8 -7.4,6.2
3D body: height 0.4, standoff 0, extent -7,5.8 -6.6,6.2
3D body: height 0.4, standoff 0, extent -6.2,5.8 -5.8,6.2
3D body: height 0.4, standoff 0, extent -5.4,5.8 -5,6.2
3D body: height 0.4, standoff 0, extent -4.6,5.8 -4.2,6.2
3D body: height 0.4, standoff 0, extent -3.8,5.8 -3.4,6.2
3D body: height 0.4, standoff 0, extent -3,5.8 -2.6,6.2
3D body: height 0.4, standoff 0, extent -2.2,5.8 -1.8,6.2
3D body: height 0.4, standoff 0, extent -1.4,5.8 -1,6.2
3D body: height 0.4, standoff 0, extent -0.6,5.8 -0.2,6.2
3D body: height 0.4, standoff 0, extent 0.2,5.8 0.6,6.2
3D body: height 0.4, standoff 0, extent 1,5.8 1.4,6.2
3D body: height 0.4, standoff 0, extent 1.8,5.8 2.2,6.2
3D body: height 0.4, standoff 0, extent 2.6,5.8 3,6.2
3D body: height 0.4, standoff 0, extent 3.4,5.8 3.8,6.2
3D body: height 0.4, standoff 0, extent 4.2,5.8 4.6,6.2
3D body: height 0.4, standoff 0, extent 5,5.8 5.4,6.2
3D body: height 0.4, standoff 0, extent 5.8,5.8 6.2,6.2
3D body: height 0.4, standoff 0, extent 6.6,5.8 7,6.2
3D body: height 0.4, standoff 0, extent 7.4,5.8 7.8,6.2
3D body: height 0.4, standoff 0, extent -7.8,5 -7.4,5.4
3D body: height 0.4, standoff 0, extent -7,5 -6.6,5.4
3D body: height 0.4, standoff 0, extent -6.2,5 -5.8,5.4
3D body: height 0.4, standoff 0, extent -5.4,5 -5,5.4
3D body: height 0.4, standoff 0, extent -4.6,5 -4.2,5.4
3D body: height 0.4, standoff 0, extent -3.8,5 -3.4,5.4
3D body: height 0.4, standoff 0, extent -3,5 -2.6,5.4
3D body: height 0.4, standoff 0, extent -2.2,5 -1.8,5.4
3D body: height 0.4, standoff 0, extent -1.4,5 -1,5.4
3D body: height 0.4, standoff 0, extent -0.6,5 -0.2,5.4
3D body: height 0.4, standoff 0, extent 0.2,5 0.6,5.4
3D body: height 0.4, standoff 0, extent 1,5 1.4,5.4
3D body: height 0.4, standoff 0, extent 1.8,5 2.2,5.4
3D body: height 0.4, standoff 0, extent 2.6,5 3,5.4
3D body: height 0.4, standoff 0, extent 3.4,5 3.8,5.4
3D body: height 0.4, standoff 0, extent 4.2,5 4.6,5.4
3D body: height 0.4, standoff 0, extent 5,5 5.4,5.4
3D body: height 0.4, standoff 0, extent 5.8,5 6.2,5.4
3D body: height 0.4, standoff 0, extent 6.6,5 7,5.4
3D body: height 0.4, standoff 0, extent 7.4,5 7.8,5.4
3D body: height 0.4, standoff 0, extent -7.8,4.2 -7.4,4.6
3D body: height 0.4, standoff 0, extent -7,4.2 -6.6,4.6
3D body: height 0.4, standoff 0, extent -6.2,4.2 -5.8,4.6
3D body: height 0.4, standoff 0, extent -5.4,4.2 -5,4.6
3D body: height 0.4, standoff 0, extent -4.6,4.2 -4.2,4.6
3D body: height 0.4, standoff 0, extent -3.8,4.2 -3.4,4.6
3D body: height 0.4, standoff 0, extent -3,4.2 -2.6,4.6
3D body: height 0.4, standoff 0, extent -2.2,4.2 -1.8,4.6
3D body: height 0.4, standoff 0, extent -1.4,4.2 -1,4.6
3D body: height 0.4, standoff 0, extent -0.6,4.2 -0.2,4.6
3D body: height 0.4, standoff 0, extent 0.2,4.2 0.6,4.6
3D body: height 0.4, standoff 0, extent 1,4.2 1.4,4.6
3D body: height 0.4, standoff 0, extent 1.8,4.2 2.2,4.6
3D body: height 0.4, standoff 0, extent 2.6,4.2 3,4.6
3D body: height 0.4, standoff 0, extent 3.4,4.2 3.8,4.6
3D body: height 0.4, standoff 0, extent 4.2,4.2 4.6,4.6
3D body: height 0.4, standoff 0, extent 5,4.2 5.4,4.6
3D body: height 0.4, standoff 0, extent 5.8,4.2 6.2,4.6
3D body: height 0.4, standoff 0, extent 6.6,4.2 7,4.6
3D body: height 0.4, standoff 0, extent 7.4,4.2 7.8,4.6
3D body: height 0.4, standoff 0, extent -7,3.4 -6.6,3.8
3D body: height 0.4, standoff 0, extent -6.2,3.4 -5.8,3.8
3D body: height 0.4, standoff 0, extent -5.4,3.4 -5,3.8
3D body: height 0.4, standoff 0, extent -4.6,3.4 -4.2,3.8
3D body: height 0.4, standoff 0, extent -3.8,3.4 -3.4,3.8
3D body: height 0.4, standoff 0, extent -3,3.4 -2.6,3.8
3D body: height 0.4, standoff 0, extent -2.2,3.4 -1.8,3.8
3D body: height 0.4, standoff 0, extent -1.4,3.4 -1,3.8
3D body: height 0.4, standoff 0, extent -0.6,3.4 -0.2,3.8
3D body: height 0.4, standoff 0, extent 0.2,3.4 0.6,3.8
3D body: height 0.4, standoff 0, extent 1,3.4 1.4,3.8
3D body: height 0.4, standoff 0, extent 1.8,3.4 2.2,3.8
3D body: height 0.4, standoff 0, extent 2.6,3.4 3,3.8
3D body: height 0.4, standoff 0, extent 3.4,3.4 3.8,3.8
3D body: height 0.4, standoff 0, extent 4.2,3.4 4.6,3.8
3D body: height 0.4, standoff 0, extent 5,3.4 5.4,3.8
3D body: height 0.4, standoff 0, extent 5.8,3.4 6.2,3.8
3D body: height 0.4, standoff 0, extent 6.6,3.4 7,3.8
3D body: height 0.4, standoff 0, extent -7,2.6 -6.6,3
3D body: height 0.4, standoff 0, extent -6.2,2.6 -5.8,3
3D body: height 0.4, standoff 0, extent -5.4,2.6 -5,3
3D body: height 0.4, standoff 0, extent -4.6,2.6 -4.2,3
3D body: height 0.4, standoff 0, extent -3.8,2.6 -3.4,3
3D body: height 0.4, standoff 0, extent -3,2.6 -2.6,3
3D body: height 0.4, standoff 0, extent -2.2,2.6 -1.8,3
3D body: height 0.4, standoff 0, extent -1.4,2.6 -1,3
3D body: height 0.4, standoff 0, extent -0.6,2.6 -0.2,3
3D body: height 0.4, standoff 0, extent 0.2,2.6 0.6,3
3D body: height 0.4, standoff 0, extent 1,2.6 1.4,3
3D body: height 0.4, standoff 0, extent 1.8,2.6 2.2,3
3D body: height 0.4, standoff 0, extent 2.6,2.6 3,3
3D body: height 0.4, standoff 0, extent 3.4,2.6 3.8,3
3D body: height 0.4, standoff 0, extent 4.2,2.6 4.6,3
3D body: height 0.4, standoff 0, extent 5,2.6 5.4,3
3D body: height 0.4, standoff 0, extent 5.8,2.6 6.2,3
3D body: height 0.4, standoff 0, extent 6.6,2.6 7,3
3D body: height 0.4, standoff 0, extent -7.8,1.8 -7.4,2.2
3D body: height 0.4, standoff 0, extent -7,1.8 -6.6,2.2
3D body: height 0.4, standoff 0, extent -6.2,1.8 -5.8,2.2
3D body: height 0.4, standoff 0, extent -5.4,1.8 -5,2.2
3D body: height 0.4, standoff 0, extent -4.6,1.8 -4.2,2.2
3D body: height 0.4, standoff 0, extent -3.8,1.8 -3.4,2.2
3D body: height 0.4, standoff 0, extent -3,1.8 -2.6,2.2
3D body: height 0.4, standoff 0, extent -2.2,1.8 -1.8,2.2
3D body: height 0.4, standoff 0, extent -1.4,1.8 -1,2.2
3D body: height 0.4, standoff 0, extent -0.6,1.8 -0.2,2.2
3D body: height 0.4, standoff 0, extent 0.2,1.8 0.6,2.2
3D body: height 0.4, standoff 0, extent 1,1.8 1.4,2.2
3D body: height 0.4, standoff 0, extent 1.8,1.8 2.2,2.2
3D body: height 0.4, standoff 0, extent 2.6,1.8 3,2.2
3D body: height 0.4, standoff 0, extent 3.4,1.8 3.8,2.2
3D body: height 0.4, standoff 0, extent 4.2,1.8 4.6,2.2
3D body: height 0.4, standoff 0, extent 5,1.8 5.4,2.2
3D body: height 0.4, standoff 0, extent 5.8,1.8 6.2,2.2
3D body: height 0.4, standoff 0, extent 6.6,1.8 7,2.2
3D body: height 0.4, standoff 0, extent 7.4,1.8 7.8,2.2
3D body: height 0.4, standoff 0, extent -7.8,1 -7.4,1.4
3D body: height 0.4, standoff 0, extent -7,1 -6.6,1.4
3D body: height 0.4, standoff 0, extent -6.2,1 -5.8,1.4
3D body: height 0.4, standoff 0, extent -5.4,1 -5,1.4
3D body: height 0.4, standoff 0, extent -4.6,1 -4.2,1.4
3D body: height 0.4, standoff 0, extent -3.8,1 -3.4,1.4
3D body: height 0.4, standoff 0, extent -3,1 -2.6,1.4
3D body: height 0.4, standoff 0, extent -2.2,1 -1.8,1.4
3D body: height 0.4, standoff 0, extent -1.4,1 -1,1.4
3D body: height 0.4, standoff 0, extent -0.6,1 -0.2,1.4
3D body: height 0.4, standoff 0, extent 0.2,1 0.6,1.4
3D body: height 0.4, standoff 0, extent 1,1 1.4,1.4
3D body: height 0.4, standoff 0, extent 1.8,1 2.2,1.4
3D body: height 0.4, standoff 0, extent 2.6,1 3,1.4
3D body: height 0.4, standoff 0, extent 3.4,1 3.8,1.4
3D body: height 0.4, standoff 0, extent 4.2,1 4.6,1.4
3D body: height 0.4, standoff 0, extent 5,1 5.4,1.4
3D body: height 0.4, standoff 0, extent 5.8,1 6.2,1.4
3D body: height 0.4, standoff 0, extent 6.6,1 7,1.4
3D body: height 0.4, standoff 0, extent 7.4,1 7.8,1.4
3D body: height 0.4, standoff 0, extent -7,0.2 -6.6,0.6
3D body: height 0.4, standoff 0, extent -6.2,0.2 -5.8,0.6
3D body: height 0.4, standoff 0, extent -5.4,0.2 -5,0.6
3D body: height 0.4, standoff 0, extent -4.6,0.2 -4.2,0.6
3D body: height 0.4, standoff 0, extent -3.8,0.2 -3.4,0.6
3D body: height 0.4, standoff 0, extent -3,0.2 -2.6,0.6
3D body: height 0.4, standoff 0, extent -2.2,0.2 -1.8,0.6
3D body: height 0.4, standoff 0, extent -1.4,0.2 -1,0.6
3D body: height 0.4, standoff 0, extent -0.6,0.2 -0.2,0.6
3D body: height 0.4, standoff 0, extent 0.2,0.2 0.6,0.6
3D body: height 0.4, standoff 0, extent 1,0.2 1.4,0.6
3D body: height 0.4, standoff 0, extent 1.8,0.2 2.2,0.6
3D body: height 0.4, standoff 0, extent 2.6,0.2 3,0.6
3D body: height 0.4, standoff 0, extent 3.4,0.2 3.8,0.6
3D body: height 0.4, standoff 0, extent 4.2,0.2 4.6,0.6
3D body: height 0.4, standoff 0, extent 5,0.2 5.4,0.6
3D body: height 0.4, standoff 0, extent 5.8,0.2 6.2,0.6
3D body: height 0.4, standoff 0, extent 6.6,0.2 7,0.6
3D body: height 0.4, standoff 0, extent -7,-0.6 -6.6,-0.2
3D body: height 0.4, standoff 0, extent -6.2,-0.6 -5.8,-0.2
3D body: height 0.4, standoff 0, extent -5.4,-0.6 -5,-0.2
3D body: height 0.4, standoff 0, extent -4.6,-0.6 -4.2,-0.2
3D body: height 0.4, standoff 0, extent -3.8,-0.6 -3.4,-0.2
3D body: height 0.4, standoff 0, extent -3,-0.6 -2.6,-0.2
3D body: height 0.4, standoff 0, extent -2.2,-0.6 -1.8,-0.2
3D body: height 0.4, standoff 0, extent -1.4,-0.6 -1,-0.2
3D body: height 0.4, standoff 0, extent -0.6,-0.6 -0.2,-0.2
3D body: height 0.4, standoff 0, extent 0.2,-0.6 0.6,-0.2
3D body: height 0.4, standoff 0, extent 1,-0.6 1.4,-0.2
3D body: height 0.4, standoff 0, extent 1.8,-0.6 2.2,-0.2
3D body: height 0.4, standoff 0, extent 2.6,-0.6 3,-0.2
3D body: height 0.4, standoff 0, extent 3.4,-0.6 3.8,-0.2
3D body: height 0.4, standoff 0, extent 4.2,-0.6 4.6,-0.2
3D body: height 0.4, standoff 0, extent 5,-0.6 5.4,-0.2
3D body: height 0.4, standoff 0, extent 5.8,-0.6 6.2,-0.2
3D body: height 0.4, standoff 0, extent 6.6,-0.6 7,-0.2
3D body: height 0.4, standoff 0, extent -7.8,-1.4 -7.4,-1
3D body: height 0.4, standoff 0, extent -7,-1.4 -6.6,-1
3D body: height 0.4, standoff 0, extent -6.2,-1.4 -5.8,-1
3D body: height 0.4, standoff 0, extent -5.4,-1.4 -5,-1
3D body: height 0.4, standoff 0, extent -4.6,-1.4 -4.2,-1
3D body: height 0.4, standoff 0, extent -3.8,-1.4 -3.4,-1
3D body: height 0.4, standoff 0, extent -3,-1.4 -2.6,-1
3D body: height 0.4, standoff 0, extent -2.2,-1.4 -1.8,-1
3D body: height 0.4, standoff 0, extent -1.4,-1.4 -1,-1
3D body: height 0.4, standoff 0, extent -0.6,-1.4 -0.2,-1
3D body: height 0.4, standoff 0, extent 0.2,-1.4 0.6,-1
3D body: height 0.4, standoff 0, extent 1,-1.4 1.4,-1
3D body: height 0.4, standoff 0, extent 1.8,-1.4 2.2,-1
3D body: height 0.4, standoff 0, extent 2.6,-1.4 3,-1
3D body: height 0.4, standoff 0, extent 3.4,-1.4 3.8,-1
3D body: height 0.4, standoff 0, extent 4.2,-1.4 4.6,-1
3D body: height 0.4, standoff 0, extent 5,-1.4 5.4,-1
3D body: height 0.4, standoff 0, extent 5.8,-1.4 6.2,-1
3D body: height 0.4, standoff 0, extent 6.6,-1.4 7,-1
3D body: height 0.4, standoff 0, extent 7.4,-1.4 7.8,-1
3D body: height 0.4, standoff 0, extent -7.8,-2.2 -7.4,-1.8
3D body: height 0.4, standoff 0, extent -7,-2.2 -6.6,-1.8
3D body: height 0.4, standoff 0, extent -6.2,-2.2 -5.8,-1.8
3D body: height 0.4, standoff 0, extent -5.4,-2.2 -5,-1.8
3D body: height 0.4, standoff 0, extent -4.6,-2.2 -4.2,-1.8
3D body: height 0.4, standoff 0, extent -3.8,-2.2 -3.4,-1.8
3D body: height 0.4, standoff 0, extent -3,-2.2 -2.6,-1.8
3D body: height 0.4, standoff 0, extent -2.2,-2.2 -1.8,-1.8
3D body: height 0.4, standoff 0, extent -1.4,-2.2 -1,-1.8
3D body: height 0.4, standoff 0, extent -0.6,-2.2 -0.2,-1.8
3D body: height 0.4, standoff 0, extent 0.2,-2.2 0.6,-1.8
3D body: height 0.4, standoff 0, extent 1,-2.2 1.4,-1.8
3D body: height 0.4, standoff 0, extent 1.8,-2.2 2.2,-1.8
3D body: height 0.4, standoff 0, extent 2.6,-2.2 3,-1.8
3D body: height 0.4, standoff 0, extent 3.4,-2.2 3.8,-1.8
3D body: height 0.4, standoff 0, extent 4.2,-2.2 4.6,-1.8
3D body: height 0.4, standoff 0, extent 5,-2.2 5.4,-1.8
3D body: height 0.4, standoff 0, extent 5.8,-2.2 6.2,-1.8
3D body: height 0.4, standoff 0, extent 6.6,-2.2 7,-1.8
3D body: height 0.4, standoff 0, extent 7.4,-2.2 7.8,-1.8
3D body: height 0.4, standoff 0, extent -7,-3 -6.6,-2.6
3D body: height 0.4, standoff 0, extent -6.2,-3 -5.8,-2.6
3D body: height 0.4, standoff 0, extent -5.4,-3 -5,-2.6
3D body: height 0.4, standoff 0, extent -4.6,-3 -4.2,-2.6
3D body: height 0.4, standoff 0, extent -3.8,-3 -3.4,-2.6
3D body: height 0.4, standoff 0, extent -3,-3 -2.6,-2.6
3D body: height 0.4, standoff 0, extent -2.2,-3 -1.8,-2.6
3D body: height 0.4, standoff 0, extent -1.4,-3 -1,-2.6
3D body: height 0.4, standoff 0, extent -0.6,-3 -0.2,-2.6
3D body: height 0.4, standoff 0, extent 0.2,-3 0.6,-2.6
3D body: height 0.4, standoff 0, extent 1,-3 1.4,-2.6
3D body: height 0.4, standoff 0, extent 1.8,-3 2.2,-2.6
3D body: height 0.4, standoff 0, extent 2.6,-3 3,-2.6
3D body: height 0.4, standoff 0, extent 3.4,-3 3.8,-2.6
3D body: height 0.4, standoff 0, extent 4.2,-3 4.6,-2.6
3D body: height 0.4, standoff 0, extent 5,-3 5.4,-2.6
3D body: height 0.4, standoff 0, extent 5.8,-3 6.2,-2.6
3D body: height 0.4, standoff 0, extent 6.6,-3 7,-2.6
3D body: height 0.4, standoff 0, extent -7,-3.8 -6.6,-3.4
3D body: height 0.4, standoff 0, extent -6.2,-3.8 -5.8,-3.4
3D body: height 0.4, standoff 0, extent -5.4,-3.8 -5,-3.4
3D body: height 0.4, standoff 0, extent -4.6,-3.8 -4.2,-3.4
3D body: height 0.4, standoff 0, extent -3.8,-3.8 -3.4,-3.4
3D body: height 0.4, standoff 0, extent -3,-3.8 -2.6,-3.4
3D body: height 0.4, standoff 0, extent -2.2,-3.8 -1.8,-3.4
3D body: height 0.4, standoff 0, extent -1.4,-3.8 -1,-3.4
3D body: height 0.4, standoff 0, extent -0.6,-3.8 -0.2,-3.4
3D body: height 0.4, standoff 0, extent 0.2,-3.8 0.6,-3.4
3D body: height 0.4, standoff 0, extent 1,-3.8 1.4,-3.4
3D body: height 0.4, standoff 0, extent 1.8,-3.8 2.2,-3.4
3D body: height 0.4, standoff 0, extent 2.6,-3.8 3,-3.4
3D body: height 0.4, standoff 0, extent 3.4,-3.8 3.8,-3.4
3D body: height 0.4, standoff 0, extent 4.2,-3.8 4.6,-3.4
3D body: height 0.4, standoff 0, extent 5,-3.8 5.4,-3.4
3D body: height 0.4, standoff 0, extent 5.8,-3.8 6.2,-3.4
3D body: height 0.4, standoff 0, extent 6.6,-3.8 7,-3.4
3D body: height 0.4, standoff 0, extent -7.8,-4.6 -7.4,-4.2
3D body: height 0.4, standoff 0, extent -7,-4.6 -6.6,-4.2
3D body: height 0.4, standoff 0, extent -6.2,-4.6 -5.8,-4.2
3D body: height 0.4, standoff 0, extent -5.4,-4.6 -5,-4.2
3D body: height 0.4, standoff 0, extent -4.6,-4.6 -4.2,-4.2
3D body: height 0.4, standoff 0, extent -3.8,-4.6 -3.4,-4.2
3D body: height 0.4, standoff 0, extent -3,-4.6 -2.6,-4.2
3D body: height 0.4, standoff 0, extent -2.2,-4.6 -1.8,-4.2
3D body: height 0.4, standoff 0, extent -1.4,-4.6 -1,-4.2
3D body: height 0.4, standoff 0, extent -0.6,-4.6 -0.2,-4.2
3D body: height 0.4, standoff 0, extent 0.2,-4.6 0.6,-4.2
3D body: height 0.4, standoff 0, extent 1,-4.6 1.4,-4.2
3D body: height 0.4, standoff 0, extent 1.8,-4.6 2.2,-4.2
3D body: height 0.4, standoff 0, extent 2.6,-4.6 3,-4.2
3D body: height 0.4, standoff 0, extent 3.4,-4.6 3.8,-4.2
3D body: height 0.4, standoff 0, extent 4.2,-4.6 4.6,-4.2
3D body: height 0.4, standoff 0, extent 5,-4.6 5.4,-4.2
3D body: height 0.4, standoff 0, extent 5.8,-4.6 6.2,-4.2
3D body: height 0.4, standoff 0, extent 6.6,-4.6 7,-4.2
3D body: height 0.4, standoff 0, extent 7.4,-4.6 7.8,-4.2
3D body: height 0.4, standoff 0, extent -7.8,-5.4 -7.4,-5
3D body: height 0.4, standoff 0, extent -7,-5.4 -6.6,-5
3D body: height 0.4, standoff 0, extent -6.2,-5.4 -5.8,-5
3D body: height 0.4, standoff 0, extent -5.4,-5.4 -5,-5
3D body: height 0.4, standoff 0, extent -4.6,-5.4 -4.2,-5
3D body: height 0.4, standoff 0, extent -3.8,-5.4 -3.4,-5
3D body: height 0.4, standoff 0, extent -3,-5.4 -2.6,-5
3D body: height 0.4, standoff 0, extent -2.2,-5.4 -1.8,-5
3D body: height 0.4, standoff 0, extent -1.4,-5.4 -1,-5
3D body: height 0.4, standoff 0, extent -0.6,-5.4 -0.2,-5
3D body: height 0.4, standoff 0, extent 0.2,-5.4 0.6,-5
3D body: height 0.4, standoff 0, extent 1,-5.4 1.4,-5
3D body: height 0.4, standoff 0, extent 1.8,-5.4 2.2,-5
3D body: height 0.4, standoff 0, extent 2.6,-5.4 3,-5
3D body: height 0.4, standoff 0, extent 3.4,-5.4 3.8,-5
3D body: height 0.4, standoff 0, extent 4.2,-5.4 4.6,-5
3D body: height 0.4, standoff 0, extent 5,-5.4 5.4,-5
3D body: height 0.4, standoff 0, extent 5.8,-5.4 6.2,-5
3D body: height 0.4, standoff 0, extent 6.6,-5.4 7,-5
3D body: height 0.4, standoff 0, extent 7.4,-5.4 7.8,-5
3D body: height 0.4, standoff 0, extent -7.8,-6.2 -7.4,-5.8
3D body: height 0.4, standoff 0, extent -7,-6.2 -6.6,-5.8
3D body: height 0.4, standoff 0, extent -6.2,-6.2 -5.8,-5.8
3D body: height 0.4, standoff 0, extent -5.4,-6.2 -5,-5.8
3D body: height 0.4, standoff 0, extent -4.6,-6.2 -4.2,-5.8
3D body: height 0.4, standoff 0, extent -3.8,-6.2 -3.4,-5.8
3D body: height 0.4, standoff 0, extent -3,-6.2 -2.6,-5.8
3D body: height 0.4, standoff 0, extent -2.2,-6.2 -1.8,-5.8
3D body: height 0.4, standoff 0, extent -1.4,-6.2 -1,-5.8
3D body: height 0.4, standoff 0, extent -0.6,-6.2 -0.2,-5.8
3D body: height 0.4, standoff 0, extent 0.2,-6.2 0.6,-5.8
3D body: height 0.4, standoff 0, extent 1,-6.2 1.4,-5.8
3D body: height 0.4, standoff 0, extent 1.8,-6.2 2.2,-5.8
3D body: height 0.4, standoff 0, extent 2.6,-6.2 3,-5.8
3D body: height 0.4, standoff 0, extent 3.4,-6.2 3.8,-5.8
3D body: height 0.4, standoff 0, extent 4.2,-6.2 4.6,-5.8
3D body: height 0.4, standoff 0, extent 5,-6.2 5.4,-5.8
3D body: height 0.4, standoff 0, extent 5.8,-6.2 6.2,-5.8
3D body: height 0.4, standoff 0, extent 6.6,-6.2 7,-5.8
3D body: height 0.4, standoff 0, extent 7.4,-6.2 7.8,-5.8
3D body: height 0.4, standoff 0, extent -7.8,-7 -7.4,-6.6
3D body: height 0.4, standoff 0, extent -7,-7 -6.6,-6.6
3D body: height 0.4, standoff 0, extent -6.2,-7 -5.8,-6.6
3D body: height 0.4, standoff 0, extent -5.4,-7 -5,-6.6
3D body: height 0.4, standoff 0, extent -4.6,-7 -4.2,-6.6
3D body: height 0.4, standoff 0, extent -3.8,-7 -3.4,-6.6
3D body: height 0.4, standoff 0, extent -3,-7 -2.6,-6.6
3D body: height 0.4, standoff 0, extent -2.2,-7 -1.8,-6.6
3D body: height 0.4, standoff 0, extent -1.4,-7 -1,-6.6
3D body: height 0.4, standoff 0, extent -0.6,-7 -0.2,-6.6
3D body: height 0.4, standoff 0, extent 0.2,-7 0.6,-6.6
3D body: height 0.4, standoff 0, extent 1,-7 1.4,-6.6
3D body: height 0.4, standoff 0, extent 1.8,-7 2.2,-6.6
3D body: height 0.4, standoff 0, extent 2.6,-7 3,-6.6
3D body: height 0.4, standoff 0, extent 3.4,-7 3.8,-6.6
3D body: height 0.4, standoff 0, extent 4.2,-7 4.6,-6.6
3D body: height 0.4, standoff 0, extent 5,-7 5.4,-6.6
3D body: height 0.4, standoff 0, extent 5.8,-7 6.2,-6.6
3D body: height 0.4, standoff 0, extent 6.6,-7 7,-6.6
3D body: height 0.4, standoff 0, extent 7.4,-7 7.8,-6.6
3D body: height 0.4, standoff 0, extent -7,-7.8 -6.6,-7.4
3D body: height 0.4, standoff 0, extent -6.2,-7.8 -5.8,-7.4
3D body: height 0.4, standoff 0, extent -5.4,-7.8 -5,-7.4
3D body: height 0.4, standoff 0, extent -4.6,-7.8 -4.2,-7.4
3D body: height 0.4, standoff 0, extent -2.2,-7.8 -1.8,-7.4
3D body: height 0.4, standoff 0, extent -1.4,-7.8 -1,-7.4
3D body: height 0.4, standoff 0, extent 1,-7.8 1.4,-7.4
3D body: height 0.4, standoff 0, extent 1.8,-7.8 2.2,-7.4
3D body: height 0.4, standoff 0, extent 4.2,-7.8 4.6,-7.4
3D body: height 0.4, standoff 0, extent 5,-7.8 5.4,-7.4
3D body: height 0.4, standoff 0, extent 5.8,-7.8 6.2,-7.4
3D body: height 0.4, standoff 0, extent 6.6,-7.8 7,-7.4
3D body: height 1.21, standoff 1.2, extent -7.1,6.5 -6.5,7.1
